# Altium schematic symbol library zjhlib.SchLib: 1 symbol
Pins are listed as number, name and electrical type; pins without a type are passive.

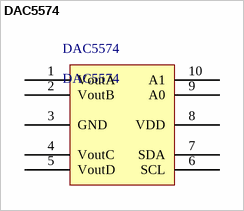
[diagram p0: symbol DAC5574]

## DAC5574
designator DAC5574
pins: 1 VoutA, 2 VoutB, 3 GND, 4 VoutC, 5 VoutD, 6 SCL, 7 SDA, 8 VDD, 9 A0, 10 A1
